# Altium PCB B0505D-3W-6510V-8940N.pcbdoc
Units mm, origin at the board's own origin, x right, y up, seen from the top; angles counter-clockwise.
Board outline 45 x 20 mm, 2 copper layers (Top Layer, Bottom Layer), stack 0.78 mm thick; 16 components, 11 nets, 42 pads, 11 vias.
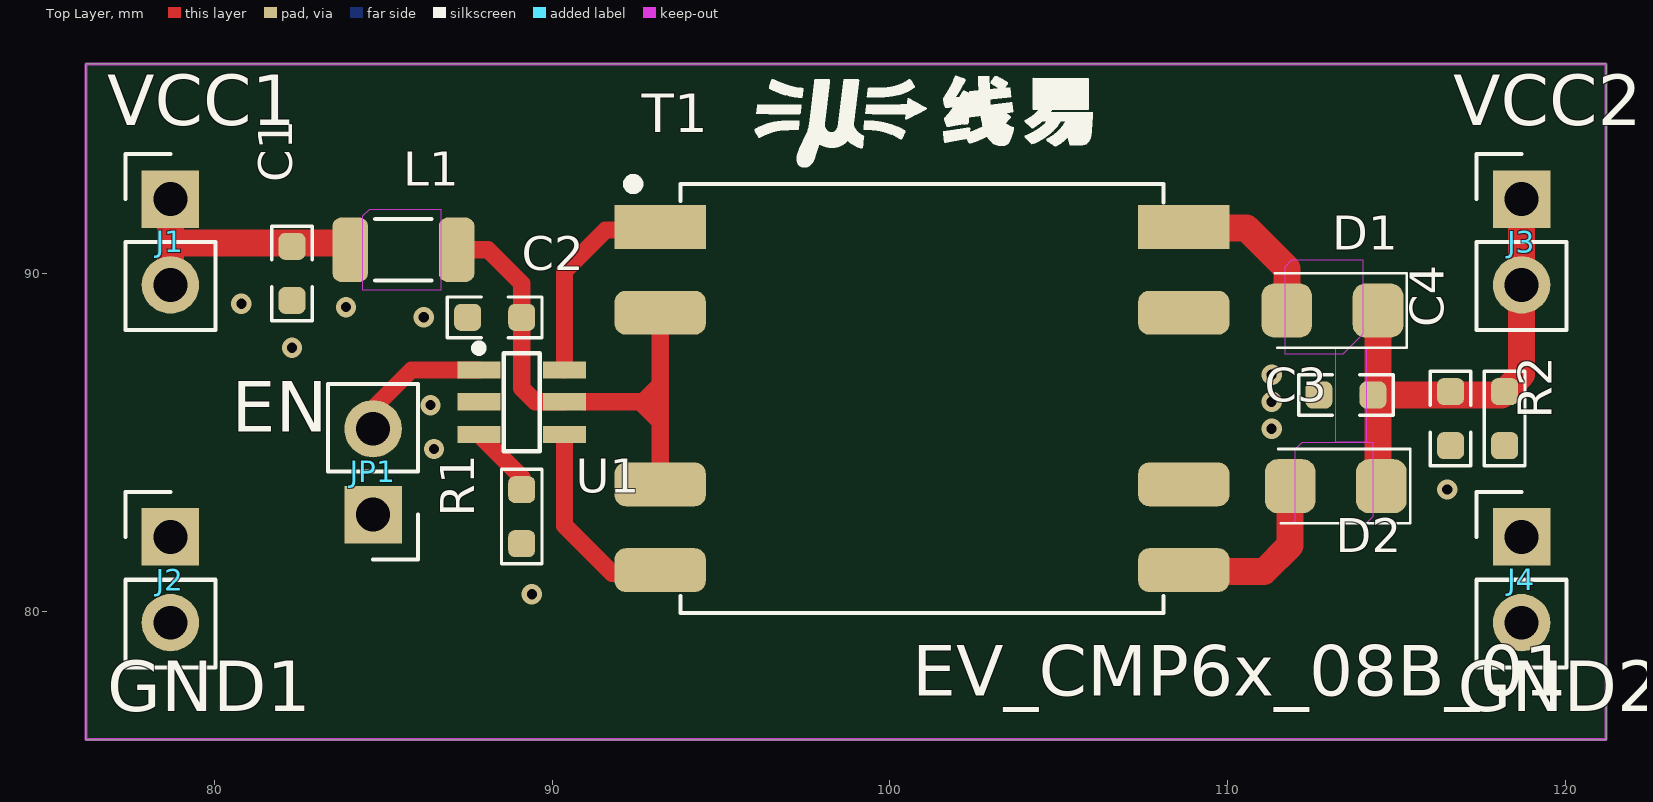
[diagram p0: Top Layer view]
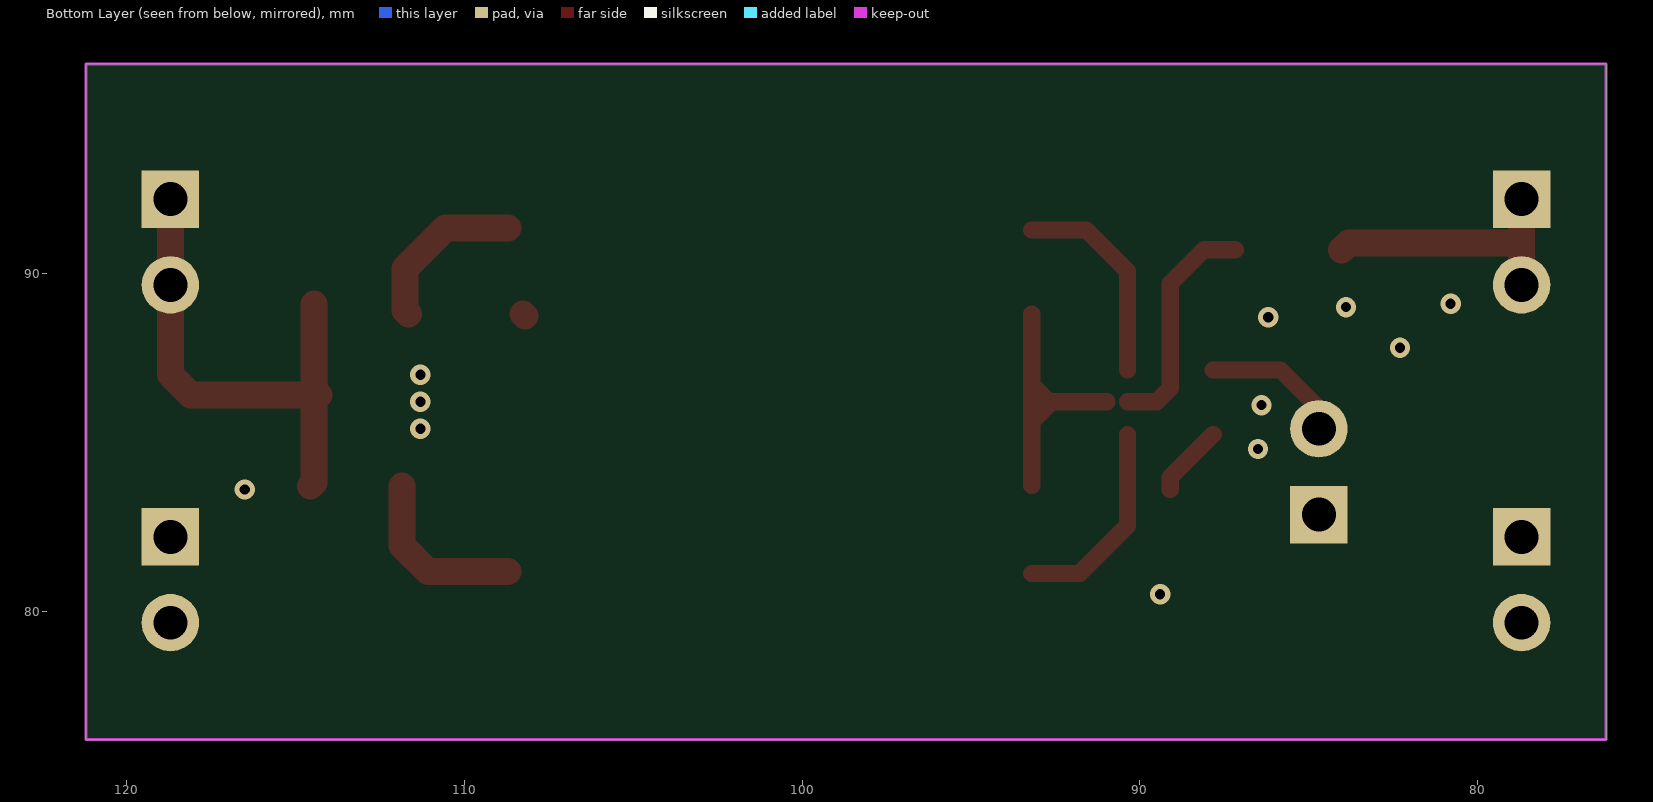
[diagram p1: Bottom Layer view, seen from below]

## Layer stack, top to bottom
Top Solder Mask Layer: solder mask 0.01, Dk 0
Top Layer: signal copper 0.035
dielectric 1: surface 0.71, FR4, Dk 4.5
Bottom Layer: signal copper 0.035
Bottom Solder Mask Layer: solder mask 0.01, Dk 0

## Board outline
76.2,96.2 121.2,96.2 121.2,76.2 76.2,76.2

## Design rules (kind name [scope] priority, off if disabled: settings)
BoardOutlineClearance copperThickness1oz [All] p0: genericclearance=0.254 ignorepadtopadclearanceinfootprint=FALSE except(0: Arc-SplitContinuation Track-SplitContinuation SMDPad-SplitContinuation THPad-SplitContinuation Via-SplitContinuation Fill-SplitContinuation Poly-SplitContinuation Region-SplitContinuation Text-SplitContinuation)
BoardOutlineClearance otherClearance [All] p0: genericclearance=0.254 ignorepadtopadclearanceinfootprint=FALSE except(0: Arc-SplitContinuation Track-SplitContinuation SMDPad-SplitContinuation THPad-SplitContinuation Via-SplitContinuation Fill-SplitContinuation Poly-SplitContinuation Region-SplitContinuation Text-SplitContinuation)
Clearance copperThickness1oz [All] p1: gap=0.178 ignorepadtopadclearanceinfootprint=FALSE
Clearance otherClearance [All] p1: gap=0.178 ignorepadtopadclearanceinfootprint=FALSE
DiffPairsRouting differentialPair [All] p1: maxuncoupledlength=10 minlimit=5 maxlimit=Infinity mostfreqgap=6 toplayer_minwidth=5 toplayer_prefwidth=100 toplayer_maxwidth=100 bottomlayer_minwidth=5 bottomlayer_prefwidth=100 bottomlayer_maxwidth=100
PasteMaskExpansion pasteMaskExpansion [All] p1: expansion=0
PlaneConnect innerPlane [All] p1: planeconnectstyle=Relief reliefexpansion=0.508 reliefentries=4 reliefconductorwidth=0.254 reliefairgap=0.254
PolygonConnect copper0 [All] p1: connectstyle=Direct reliefentries=4 reliefconductorwidth=10 polygonreliefangle="90 Angle" airgapwidth=10
PolygonConnect copper1 [All] p1: connectstyle=Direct reliefentries=4 reliefconductorwidth=10 polygonreliefangle="90 Angle" airgapwidth=10
RoutingVias viaSize [All] p1: viastyle="Through Hole" holewidth=24 minholewidth=11.811 maxholewidth=393.7 width=24 minwidth=11.811 maxwidth=393.7
SolderMaskExpansion solderMaskExpansion [All] p1: useseparateexpansions=TRUE expansion=2 expansionbottom=2
Width copperThickness1oz [All] p1: maxlimit=100 minlimit=5 preferedwidth=10

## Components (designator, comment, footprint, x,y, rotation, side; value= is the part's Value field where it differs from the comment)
C1 "My_Library_C" MYLibrary:C0603 82.3,90 r90 top
C2 "10uF" C0603 88.3,88.7 r0 top
C3 "10uF" C0603 113.5,86.4 r0 top
C4 "100nF" C0603 116.6,85.7 r90 top
D1 "DSS34" SOD-123FL_L2.7-W1.8-LS3.8-RD 113.1,88.9 r180 top
D2 "DSS34" SOD-123FL_L2.7-W1.8-LS3.8-RD 113.2,83.7 r180 top
J1 "HX PZ2.54-1x2P ZZ" HDR-TH_2P-P2.54-V-M-3 78.7,92.2 r0 top
J2 "HX PZ2.54-1x2P ZZ" HDR-TH_2P-P2.54-V-M-3 78.7,82.2 r0 top
J3 "HX PZ2.54-1x2P ZZ" HDR-TH_2P-P2.54-V-M-3 118.7,92.2 r0 top
J4 "HX PZ2.54-1x2P ZZ" HDR-TH_2P-P2.54-V-M-3 118.7,82.2 r0 top
JP1 "HX PZ2.54-1x2P ZZ" HDR-TH_2P-P2.54-V-M-3 84.7,82.86 r180 top
L1 "0Ω" R1206 85.6,90.7 r0 top
R1 "My_Library_R" MYLibrary:R0603 89.1,82.8 r90 top
R2 "2.2kΩ" R0603 118.2,85.7 r270 top
T1 "MYLibrary _CMT8940N" MYLibrary:CMT8940N 101.204,86.638 r0 top
U1 "CMP6510V" SOT-23-6_L2.9-W1.6-P0.95-LS2.8-BR 89.1,86.2 r0 top

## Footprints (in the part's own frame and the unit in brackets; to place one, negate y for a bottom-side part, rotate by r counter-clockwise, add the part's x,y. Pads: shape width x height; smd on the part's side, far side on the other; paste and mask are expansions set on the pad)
C0603 [mm]
  rrect50% 0.8x0.8 smd: 1(-0.8,0) 2(0.8,0)
  silkscreen extent -1.4,-0.6 1.4,0.6
HDR-TH_2P-P2.54-V-M-3 [mm]
  rect 1.7x1.7 hole 1: 1(0,0)
  round 1.7 hole 1: 2(0,-2.54)
  silkscreen extent -1.33,-3.87 1.33,1.33
MYLibrary:C0603 [mm]
  rrect50% 0.8x0.8 smd: 1(-0.8,0) 2(0.8,0)
  silkscreen extent -1.4,-0.6 1.4,0.6
MYLibrary:CMT8940N [mm]
  rect 2.7x1.3 smd: 1(-8.004,4.737) 8(7.496,4.737)
  rrect50% 2.7x1.3 smd: 2(-8.004,2.197) 3(-8.004,-2.883) 4(-8.004,-5.423) 5(7.496,-5.423) 6(7.496,-2.883) 7(7.496,2.197)
  silkscreen extent -8.95,-6.69 6.9,6.16
MYLibrary:R0603 [mm]
  rrect50% 0.8x0.8 smd: 1(-0.8,0) 2(0.8,0)
  silkscreen extent -1.4,-0.6 1.4,0.6
R0603 [mm]
  rrect50% 0.8x0.8 smd: 1(-0.8,0) 2(0.8,0)
  silkscreen extent -1.4,-0.6 1.4,0.6
R1206 [mm]
  rrect47% 1.05x1.9 smd: 1(-1.575,0) 2(1.575,0)
  silkscreen extent -0.84,-0.91 0.84,0.91
SOD-123FL_L2.7-W1.8-LS3.8-RD [mm]
  rrect50% 1.5x1.6 smd: 1(-1.35,0) 2(1.35,0)
  silkscreen extent -2.2,-1.1 1.7,1.1
SOT-23-6_L2.9-W1.6-P0.95-LS2.8-BR [mil]
  rect 50x20 smd: 1(-50,37) 2(-50,0) 3(-50,-38) 4(50,-38) 5(50,0) 6(50,37)
  silkscreen extent -54,-58 21,66

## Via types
v1: diameter 0.6, hole 0.3, Top Layer to Bottom Layer, 11 vias

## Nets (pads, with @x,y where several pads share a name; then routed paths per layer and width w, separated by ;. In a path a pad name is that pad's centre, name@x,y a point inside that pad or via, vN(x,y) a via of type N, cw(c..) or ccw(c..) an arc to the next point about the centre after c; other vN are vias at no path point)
$1N1: C2.2 L1.2 T1.2 T1.3 U1.5 | length 15.7
  Top Layer w0.508: L1.2 88.1,90.7 89.1,89.7 C2.2 89.1,86.6 89.5,86.2 U1.5 ; U1.5@90.97,86.2 92.6,86.2 ; T1.3@93.2,83.717 93.2,85.6 ; T1.2@93.2,88.797 93.2,86.7 ; 92.6,86.2 93.2,85.6 ; 92.6,86.2 92.7,86.2 ; 92.7,86.2 93.2,86.7 ; 92.7,86.2 93.2,86.2 ; 93.2,85.6 93.2,86.2 ; 93.2,86.2 93.2,86.7
$1N5: D2.2 T1.5 | length 5.2
  Top Layer w0.8: T1.5@108.7,81.177 111.077,81.177 111.85,81.95 D2.2
$1N6: T1.4 U1.4 | length 6.1
  Top Layer w0.508: U1.4 90.37,82.53 91.78,81.12 T1.4@93.2,81.12
$1N7: D1.2 T1.8 | length 4.9
  Top Layer w0.8: T1.8@108.7,91.337 110.563,91.337 111.75,90.15 D1.2 D1.2@111.65,88.8
$1N8: T1.1 U1.6 | length 6.3
  Top Layer w0.508: U1.6 90.37,90.07 91.58,91.28 T1.1@93.2,91.28
$1N10: R1.2 U1.3 | length 2.2
  Top Layer w0.508: U1.3 89.1,83.965 R1.2
EN: JP1.2 U1.1 | length 4.2
  Top Layer w0.508: JP1.2 84.7,86 85.84,87.14 U1.1
GND1: C1.1 C2.1 J2.1 J2.2 JP1.1 R1.1 U1.2
  other v1: 89.4,80.5 86.5,84.8 86.4,86.1 82.3,87.8 86.2,88.7 83.9,89 80.8,89.1
GND2: C3.1 C4.1 J4.1 J4.2 R2.2 T1.6 T1.7 | length 0.1
  Top Layer w0.8: T1.7@108.2,88.74 T1.7@108.26,88.8
  other v1: 116.5,83.6 111.3,85.4 111.3,86.2 111.3,87
VCC1: C1.2 J1.1 J1.2 L1.1 | length 8
  Top Layer w0.8: J1.2 78.7,90.8 ; J1.1 78.7,90.8 ; L1.1 83.825,90.9 78.8,90.9 78.7,90.8
VCC2: C3.2 C4.2 D1.1 D2.1 J3.1 J3.2 R2.1 | length 15.3
  Top Layer w0.8: C3.2 C3.2@114.45,86.4 ; D1.1@114.45,89.1 C3.2@114.45,86.4 ; D2.1 114.45,83.8 C3.2@114.45,86.4 ; J3.1 J3.2 118.7,87 R2.1 118.1,86.4 C3.2@114.45,86.4

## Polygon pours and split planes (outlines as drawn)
GND1 on Top Layer (solid, remove dead copper, pour order 4): 76.2,96.2 94.6,96.2 94.6,76.2 76.2,76.2
GND2 on Top Layer (solid, remove dead copper, pour order 8): 107.2,96.2 121.2,96.2 121.2,76.2 107.2,76.2
GND1 on Bottom Layer (solid, remove dead copper, pour order 12): 76.2,96.2 94.6,96.2 94.6,76.2 76.2,76.2
GND2 on Bottom Layer (solid, remove dead copper, pour order 16): 107.2,96.2 121.2,96.2 121.2,76.2 107.2,76.2
GND2 on Top Layer (solid, remove dead copper, pour order 2): 107.35,89.447 114.55,89.447 114.55,83.047 107.35,83.047

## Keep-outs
Top Layer:
  region: 114,90.4 114,88.2 113.4,87.6 111.7,87.6 111.7,90.2 111.9,90.4
  region: 86.7,91.9 86.7,89.5 84.4,89.5 84.4,91.7 84.6,91.9
  region: 114.1,87.8 114.1,85 113.7,85 113.2,85 113.2,87.8
  region: 114.3,85 114.3,82.8 114.1,82.6 112,82.6 112,84.8 112.2,85
Board Outline Layer:
  the board outline again, w0.1

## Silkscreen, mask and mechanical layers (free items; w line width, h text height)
Top Silkscreen Layer:
  drawing of 9 lines, arcs and shapes, not listed
  text "VCC1" at 76.827,94.381 h1.5
  text "VCC2" at 116.678,94.381 h1.5
  text "EN" at 80.51,85.314 h1.5
  text "EV_CMP6x_08B_01" at 100.662,77.5 h1.5
  text "GND1" at 76.827,77.035 h1.5
  text "GND2" at 116.805,77.035 h1.5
